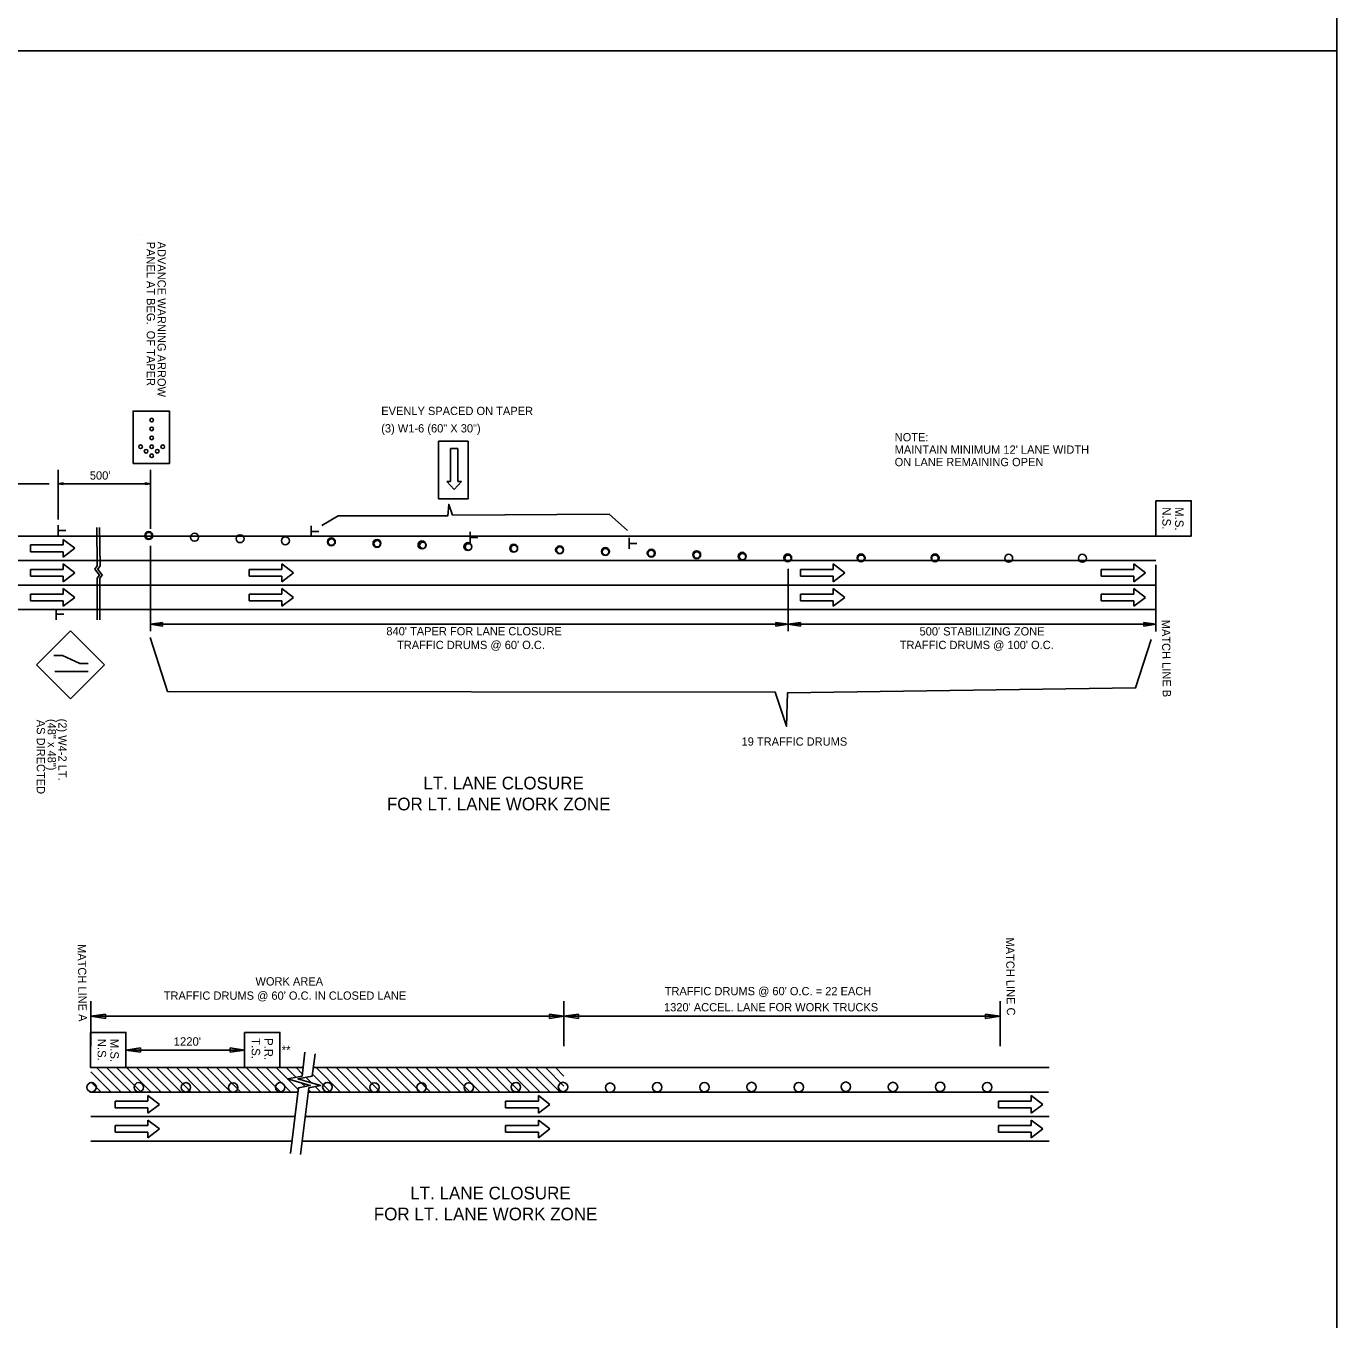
# Model space of a CAD drawing. Extents: x -100 to 745, y -1581 to -107.
# Drawn here: x 252.5 to 345.4, y -460.6 to -368.8 of the extents above; entities that cross this region are included whole.
import ezdxf

# ---------------------------------------------------------------- set-up
doc = ezdxf.new("R2010")
doc.units = 0
for name, color, linetype in [('Default', 7, 'Continuous'), ('R_Contour Annot', 7, 'Continuous'), ('R_Draft', 7, 'Continuous'), ('R_ROW', 7, 'Continuous'), ('R_ROW Annot', 7, 'Continuous')]:
    doc.layers.add(name, color=color, linetype=linetype)

msp = doc.modelspace()

# ---------------------------------------------------------------- linework, layer by layer
at = {"layer": 'Default'}
for p, q in [((282.592, -398.789), (282.592, -401.12)), ((282.592, -398.789), (283.111, -398.789)), ((283.111, -398.789), (283.111, -401.12)), ((254.765, -400.299), (254.765, -403.82)), ((261.312, -400.299), (261.312, -404.481)), ((248.914, -401.278), (254.133, -401.278)), ((255.14, -401.222), (254.765, -401.278)), ((254.765, -401.278), (261.312, -401.278)), ((255.14, -401.335), (254.765, -401.278)), ((255.14, -401.232), (254.828, -401.278)), ((255.14, -401.325), (254.828, -401.278)), ((255.14, -401.241), (254.892, -401.278)), ((255.14, -401.316), (254.892, -401.278)), ((255.14, -401.25), (254.955, -401.278)), ((255.14, -401.306), (254.955, -401.278)), ((255.14, -401.26), (255.018, -401.278)), ((255.14, -401.297), (255.018, -401.278)), ((255.14, -401.27), (255.081, -401.278)), ((255.14, -401.287), (255.081, -401.278)), ((255.14, -401.335), (255.14, -401.222)), ((260.937, -401.222), (261.312, -401.278)), ((260.937, -401.222), (260.937, -401.335)), ((260.937, -401.232), (261.25, -401.278)), ((260.937, -401.241), (261.185, -401.278)), ((260.937, -401.25), (261.123, -401.278)), ((260.937, -401.26), (261.059, -401.278)), ((260.937, -401.27), (260.997, -401.278)), ((260.937, -401.335), (261.312, -401.278)), ((260.937, -401.297), (261.059, -401.278)), ((260.937, -401.316), (261.185, -401.278)), ((260.937, -401.325), (261.25, -401.278)), ((260.937, -401.306), (261.123, -401.278)), ((260.937, -401.287), (260.997, -401.278)), ((282.592, -401.12), (282.333, -401.12)), ((282.333, -401.12), (282.851, -401.689)), ((282.851, -401.689), (283.371, -401.12)), ((283.111, -401.12), (283.371, -401.12)), ((245.32, -404.99), (261.312, -404.99)), ((254.765, -404.994), (254.765, -404.212)), ((254.777, -404.605), (255.311, -404.605)), ((261.312, -404.99), (332.591, -404.99)), ((272.715, -404.268), (272.715, -405.05)), ((272.727, -404.657), (273.261, -404.657)), ((283.986, -404.694), (283.986, -405.477)), ((255.132, -405.622), (252.807, -405.622)), ((252.807, -405.622), (252.807, -406.097)), ((255.132, -405.227), (255.132, -405.622)), ((255.132, -405.227), (255.953, -405.859)), ((255.953, -405.859), (255.132, -406.492)), ((261.312, -411.735), (261.312, -405.691)), ((283.997, -405.083), (284.532, -405.083)), ((295.257, -405.121), (295.257, -405.903)), ((295.268, -405.51), (295.802, -405.51)), ((245.32, -406.729), (261.312, -406.729)), ((255.132, -406.097), (252.807, -406.097)), ((255.132, -406.097), (255.132, -406.492)), ((261.312, -406.729), (332.591, -406.729)), ((255.132, -407.361), (252.807, -407.361)), ((252.807, -407.361), (252.807, -407.835)), ((255.132, -406.966), (255.132, -407.361)), ((255.132, -406.966), (255.953, -407.598)), ((255.953, -407.598), (255.132, -408.23)), ((270.63, -407.361), (268.304, -407.361)), ((268.304, -407.361), (268.304, -407.835)), ((270.63, -406.966), (270.63, -407.361)), ((270.63, -406.966), (271.451, -407.598)), ((271.451, -407.598), (270.63, -408.23)), ((306.513, -411.735), (306.513, -407.306)), ((309.709, -407.361), (307.384, -407.361)), ((307.384, -407.361), (307.384, -407.835)), ((309.709, -406.966), (309.709, -407.361)), ((309.709, -406.966), (310.53, -407.598)), ((310.53, -407.598), (309.709, -408.23)), ((331.029, -407.361), (328.703, -407.361)), ((328.703, -407.361), (328.703, -407.835)), ((331.029, -406.966), (331.029, -407.361)), ((331.029, -406.966), (331.849, -407.598)), ((331.849, -407.598), (331.029, -408.23)), ((332.591, -407.028), (332.591, -411.745)), ((245.32, -408.467), (261.312, -408.467)), ((255.132, -407.835), (252.807, -407.835)), ((255.132, -407.835), (255.132, -408.23)), ((255.132, -408.704), (255.132, -409.099)), ((255.132, -408.704), (255.953, -409.336)), ((261.312, -408.467), (332.591, -408.467)), ((270.63, -407.835), (268.304, -407.835)), ((270.63, -407.835), (270.63, -408.23)), ((270.63, -408.704), (270.63, -409.099)), ((270.63, -408.704), (271.451, -409.336)), ((309.709, -407.835), (307.384, -407.835)), ((309.709, -407.835), (309.709, -408.23)), ((309.709, -408.704), (309.709, -409.099)), ((309.709, -408.704), (310.53, -409.336)), ((331.029, -407.835), (328.703, -407.835)), ((331.029, -407.835), (331.029, -408.23)), ((331.029, -408.704), (331.029, -409.099)), ((331.029, -408.704), (331.849, -409.336)), ((255.132, -409.099), (252.807, -409.099)), ((252.807, -409.099), (252.807, -409.574)), ((255.132, -409.574), (252.807, -409.574)), ((255.953, -409.336), (255.132, -409.969)), ((255.132, -409.574), (255.132, -409.969)), ((270.63, -409.099), (268.304, -409.099)), ((268.304, -409.099), (268.304, -409.574)), ((270.63, -409.574), (268.304, -409.574)), ((271.451, -409.336), (270.63, -409.969)), ((270.63, -409.574), (270.63, -409.969)), ((309.709, -409.099), (307.384, -409.099)), ((307.384, -409.099), (307.384, -409.574)), ((309.709, -409.574), (307.384, -409.574)), ((310.53, -409.336), (309.709, -409.969)), ((309.709, -409.574), (309.709, -409.969)), ((331.029, -409.099), (328.703, -409.099)), ((328.703, -409.099), (328.703, -409.574)), ((331.029, -409.574), (328.703, -409.574)), ((331.849, -409.336), (331.029, -409.969)), ((331.029, -409.574), (331.029, -409.969)), ((245.32, -410.206), (261.312, -410.206)), ((254.639, -410.924), (254.639, -410.141)), ((254.65, -410.535), (255.184, -410.535)), ((261.312, -410.206), (332.591, -410.206)), ((262.182, -411.115), (261.312, -411.246)), ((306.513, -411.246), (261.312, -411.246)), ((261.312, -411.246), (262.182, -411.376)), ((262.182, -411.376), (262.182, -411.115)), ((306.513, -411.246), (305.644, -411.115)), ((305.644, -411.115), (305.644, -411.376)), ((305.644, -411.376), (306.513, -411.246)), ((307.383, -411.115), (306.513, -411.246)), ((332.591, -411.246), (306.513, -411.246)), ((306.513, -411.246), (307.383, -411.376)), ((307.383, -411.376), (307.383, -411.115)), ((332.591, -411.246), (331.722, -411.115)), ((331.722, -411.115), (331.722, -411.376)), ((331.722, -411.376), (332.591, -411.246)), ((255.646, -411.709), (253.237, -414.119)), ((255.646, -411.709), (258.056, -414.119)), ((253.237, -414.119), (255.646, -416.528)), ((254.479, -413.458), (255.092, -413.458)), ((255.092, -413.458), (256.317, -414.02)), ((258.056, -414.119), (255.646, -416.528)), ((256.317, -414.02), (256.9, -414.02)), ((254.53, -414.582), (256.9, -414.582)), ((257.095, -437.957), (257.095, -441.149)), ((290.63, -437.957), (290.63, -441.149)), ((321.54, -437.957), (321.54, -441.149)), ((257.095, -439.036), (258.125, -438.881)), ((290.63, -439.036), (257.095, -439.036)), ((258.125, -439.19), (257.095, -439.036)), ((258.125, -438.881), (258.125, -439.19)), ((289.6, -439.19), (289.6, -438.882)), ((289.6, -438.882), (290.63, -439.036)), ((290.63, -439.036), (289.6, -439.19)), ((290.63, -439.036), (291.66, -438.881)), ((321.54, -439.036), (290.63, -439.036)), ((291.66, -439.19), (290.63, -439.036)), ((291.66, -438.881), (291.66, -439.19)), ((320.51, -439.19), (320.51, -438.881)), ((320.51, -438.881), (321.54, -439.036)), ((321.54, -439.036), (320.51, -439.19)), ((257.095, -439.695), (257.095, -441.149)), ((257.095, -440.627), (257.095, -441.149)), ((259.573, -441.424), (260.604, -441.269)), ((267.994, -441.424), (259.573, -441.424)), ((260.604, -441.578), (259.573, -441.424)), ((260.604, -441.269), (260.604, -441.578)), ((266.964, -441.578), (266.964, -441.269)), ((266.964, -441.269), (267.994, -441.424)), ((267.994, -441.424), (266.964, -441.578)), ((257.073, -442.674), (272.134, -442.674)), ((257.096, -442.973), (258.535, -444.412)), ((257.504, -442.674), (259.242, -444.412)), ((258.211, -442.674), (260.004, -444.468)), ((258.918, -442.674), (260.656, -444.412)), ((259.625, -442.674), (261.363, -444.412)), ((260.332, -442.674), (262.07, -444.412)), ((261.039, -442.674), (262.777, -444.412)), ((261.746, -442.674), (263.485, -444.412)), ((262.453, -442.674), (264.192, -444.412)), ((263.16, -442.674), (264.899, -444.412)), ((263.868, -442.674), (265.606, -444.412)), ((264.575, -442.674), (266.313, -444.412)), ((265.282, -442.674), (267.02, -444.412)), ((265.989, -442.674), (267.727, -444.412)), ((266.696, -442.674), (268.434, -444.412)), ((267.403, -442.674), (269.141, -444.412)), ((268.11, -442.674), (269.849, -444.412)), ((268.817, -442.674), (270.556, -444.412)), ((269.524, -442.674), (271.263, -444.412)), ((270.232, -442.674), (271.801, -444.243)), ((270.939, -442.674), (271.62, -443.355)), ((271.646, -442.674), (272.082, -443.11)), ((272.863, -442.673), (290.63, -442.673)), ((273.06, -442.674), (274.798, -444.412)), ((273.767, -442.674), (275.505, -444.412)), ((274.474, -442.674), (276.212, -444.412)), ((275.181, -442.674), (276.92, -444.412)), ((275.888, -442.674), (277.627, -444.412)), ((276.596, -442.674), (278.334, -444.412)), ((277.303, -442.674), (279.041, -444.412)), ((278.01, -442.674), (279.748, -444.412)), ((278.717, -442.674), (280.455, -444.412)), ((279.424, -442.674), (281.162, -444.412)), ((280.131, -442.674), (281.869, -444.412)), ((280.838, -442.674), (282.576, -444.412)), ((281.545, -442.674), (283.284, -444.412)), ((282.252, -442.674), (283.991, -444.412)), ((282.959, -442.674), (284.698, -444.412)), ((283.667, -442.674), (285.405, -444.412)), ((284.374, -442.674), (286.112, -444.412)), ((285.081, -442.674), (286.819, -444.412)), ((285.788, -442.674), (287.526, -444.412)), ((286.495, -442.674), (288.233, -444.412)), ((287.202, -442.674), (288.94, -444.412)), ((287.909, -442.674), (289.647, -444.412)), ((288.616, -442.674), (290.355, -444.412)), ((289.323, -442.674), (290.63, -443.981)), ((290.031, -442.674), (290.63, -443.274)), ((290.63, -442.673), (325.019, -442.673)), ((257.096, -443.68), (257.828, -444.412)), ((272.029, -443.764), (272.28, -444.015)), ((272.33, -443.358), (272.727, -443.755)), ((272.808, -443.129), (274.091, -444.412)), ((272.99, -444.018), (273.384, -444.412)), ((257.025, -444.412), (271.78, -444.412)), ((261.133, -445.044), (261.133, -444.649)), ((261.954, -445.281), (261.133, -444.649)), ((272.508, -444.412), (290.63, -444.412)), ((272.527, -444.262), (272.677, -444.412)), ((288.812, -445.044), (288.812, -444.649)), ((289.632, -445.281), (288.812, -444.649)), ((290.581, -444.411), (324.97, -444.411)), ((323.754, -445.044), (323.754, -444.649)), ((324.575, -445.281), (323.754, -444.649)), ((261.133, -445.044), (258.808, -445.044)), ((258.808, -445.518), (258.808, -445.044)), ((261.133, -445.518), (258.808, -445.518)), ((261.133, -445.913), (261.954, -445.281)), ((261.133, -445.913), (261.133, -445.518)), ((288.812, -445.044), (286.486, -445.044)), ((286.486, -445.518), (286.486, -445.044)), ((288.812, -445.518), (286.486, -445.518)), ((288.812, -445.913), (289.632, -445.281)), ((288.812, -445.913), (288.812, -445.518)), ((323.754, -445.044), (321.429, -445.044)), ((321.429, -445.518), (321.429, -445.044)), ((323.754, -445.518), (321.429, -445.518)), ((323.754, -445.913), (324.575, -445.281)), ((323.754, -445.913), (323.754, -445.518)), ((257.095, -446.15), (271.563, -446.15)), ((261.133, -446.782), (258.808, -446.782)), ((258.808, -447.257), (258.808, -446.782)), ((261.133, -446.782), (261.133, -446.387)), ((261.954, -447.02), (261.133, -446.387)), ((272.34, -446.15), (290.63, -446.15)), ((288.812, -446.782), (286.486, -446.782)), ((286.486, -447.257), (286.486, -446.782)), ((288.812, -446.782), (288.812, -446.387)), ((289.632, -447.02), (288.812, -446.387)), ((290.63, -446.15), (325.019, -446.15)), ((323.754, -446.782), (321.429, -446.782)), ((321.429, -447.257), (321.429, -446.782)), ((323.754, -446.782), (323.754, -446.387)), ((324.575, -447.02), (323.754, -446.387)), ((261.133, -447.257), (258.808, -447.257)), ((261.133, -447.652), (261.954, -447.02)), ((261.133, -447.652), (261.133, -447.257)), ((288.812, -447.257), (286.486, -447.257)), ((288.812, -447.652), (289.632, -447.02)), ((288.812, -447.652), (288.812, -447.257)), ((323.754, -447.257), (321.429, -447.257)), ((323.754, -447.652), (324.575, -447.02)), ((323.754, -447.652), (323.754, -447.257)), ((257.095, -447.888), (271.346, -447.888)), ((272.074, -447.888), (290.63, -447.888)), ((290.63, -447.888), (325.019, -447.888))]:
    msp.add_line(p, q, dxfattribs=at)
for points in [[(260.087, -399.851), (260.087, -396.128), (262.663, -396.128), (262.663, -399.851)], [(281.738, -402.355), (281.738, -398.268), (283.828, -398.268), (283.828, -402.355)], [(332.591, -402.49), (335.091, -402.49), (335.091, -404.99), (332.591, -404.99)], [(257.073, -440.174), (259.573, -440.174), (259.573, -442.674), (257.073, -442.674)], [(267.994, -440.174), (270.494, -440.174), (270.494, -442.674), (267.994, -442.674)]]:
    msp.add_lwpolyline(points, close=True, dxfattribs=at)
for points in [[(273.468, -404.247), (274.626, -403.566), (282.391, -403.566), (282.459, -402.748), (282.731, -403.497), (293.835, -403.429), (295.129, -404.588)], [(257.506, -404.379), (257.548, -407.089), (257.385, -407.331), (257.702, -407.764), (257.535, -407.964), (257.534, -410.917)], [(257.706, -404.379), (257.747, -407.098), (257.585, -407.339), (257.901, -407.772), (257.735, -407.972), (257.734, -410.917)], [(261.302, -412.175), (262.535, -416.009), (305.6, -416.059), (306.406, -418.478), (306.479, -416.093), (331.147, -415.76), (332.256, -412.325)], [(271.238, -448.753), (271.819, -444.097), (272.645, -443.951), (271.042, -443.465), (272.062, -443.271), (272.265, -441.586)], [(271.955, -448.843), (272.548, -444.097), (273.373, -443.951), (271.771, -443.465), (272.791, -443.271), (272.981, -441.69)]]:
    msp.add_lwpolyline(points, dxfattribs=at)
for centre, radius in [((261.404, -396.764), 0.131), ((261.404, -397.396), 0.131), ((261.404, -398.029), 0.131), ((260.615, -398.661), 0.131), ((261.01, -398.977), 0.131), ((261.404, -398.661), 0.131), ((261.404, -399.294), 0.131), ((261.799, -398.977), 0.131), ((262.194, -398.661), 0.131), ((261.193, -404.957), 0.281), ((261.205, -404.958), 0.229), ((264.442, -405.072), 0.281), ((267.674, -405.175), 0.281), ((270.884, -405.32), 0.281), ((274.141, -405.397), 0.281), ((274.152, -405.416), 0.229), ((277.374, -405.508), 0.281), ((277.389, -405.531), 0.229), ((280.563, -405.618), 0.281), ((280.626, -405.646), 0.229), ((283.814, -405.734), 0.281), ((283.863, -405.76), 0.229), ((287.064, -405.851), 0.281), ((287.1, -405.875), 0.229), ((290.314, -405.967), 0.281), ((290.336, -405.99), 0.229), ((293.564, -406.083), 0.281), ((293.573, -406.104), 0.229), ((296.814, -406.2), 0.281), ((296.81, -406.219), 0.229), ((300.035, -406.31), 0.281), ((300.047, -406.334), 0.229), ((303.26, -406.421), 0.281), ((303.284, -406.449), 0.229), ((306.485, -406.531), 0.281), ((306.508, -406.564), 0.229), ((306.52, -406.563), 0.229), ((311.69, -406.531), 0.281), ((311.697, -406.562), 0.229), ((316.932, -406.532), 0.281), ((316.924, -406.562), 0.229), ((322.151, -406.562), 0.281), ((327.378, -406.562), 0.281), ((257.15, -444.07), 0.333), ((260.491, -444.07), 0.333), ((263.832, -444.071), 0.333), ((267.174, -444.091), 0.333), ((270.515, -444.07), 0.333), ((273.856, -444.059), 0.333), ((277.197, -444.075), 0.333), ((280.538, -444.075), 0.333), ((283.879, -444.075), 0.333), ((287.22, -444.059), 0.333), ((290.561, -444.047), 0.333), ((293.902, -444.095), 0.333), ((297.243, -444.063), 0.333), ((300.584, -444.063), 0.333), ((303.925, -444.047), 0.333), ((307.266, -444.06), 0.333), ((310.607, -444.025), 0.333), ((313.948, -444.047), 0.333), ((317.289, -444.044), 0.333), ((320.63, -444.06), 0.333)]:
    msp.add_circle(centre, radius, dxfattribs=at)
at = {"layer": 'R_Contour Annot'}
for points in [[(175.406, -260.582), (345.406, -260.582), (345.406, -370.582), (175.406, -370.582)], [(175.406, -370.582), (345.406, -370.582), (345.406, -480.582), (175.406, -480.582)]]:
    msp.add_lwpolyline(points, close=True, dxfattribs=at)
at = {"layer": 'R_Draft'}
for points in [[(175.406, -260.582), (175.406, -370.582), (345.406, -370.582), (345.406, -260.582)], [(175.406, -370.582), (175.406, -480.582), (345.406, -480.582), (345.406, -370.582)]]:
    msp.add_lwpolyline(points, close=True, dxfattribs=at)
at = {"layer": 'R_ROW Annot'}
msp.add_line((260.692, -383.596), (260.692, -383.596), dxfattribs=at)
msp.add_line((260.692, -383.596), (260.692, -383.596), dxfattribs=at)

# ---------------------------------------------------------------- texts
at = {"layer": 'Default'}
for s, height, rotation, p in [('PANEL AT BEG.  OF TAPER', 0.5862, 270, (261.055, -384.115)), ('ADVANCE WARNING ARROW', 0.5862, 270, (261.819, -384.115)), ('EVENLY SPACED ON TAPER', 0.5862, 359.99246, (277.676, -396.409)), ('(3) W1-6 (60" X 30")', 0.5862, 359.99246, (277.676, -397.644)), ('N.S.', 0.6, 270, (333.044, -402.949)), ('M.S.', 0.6, 270, (333.944, -402.949)), ('MATCH LINE B', 0.5862, 270.80593, (332.997, -410.926)), ('AS DIRECTED', 0.5862, 270, (253.261, -418.013)), ('(48" x 48")', 0.5862, 270, (254.033, -417.956)), ('(2) W4-2 LT.', 0.5862, 270, (254.79, -417.932)), ('MATCH LINE C', 0.5862, 270.80593, (321.947, -433.454)), ('MATCH LINE A', 0.5862, 270.80593, (256.152, -433.917)), ('N.S.', 0.6, 270, (257.573, -440.632)), ('M.S.', 0.6, 270, (258.473, -440.632)), ('T.S.', 0.6, 270, (268.494, -440.585)), ('P.R.', 0.6, 270, (269.394, -440.585))]:
    msp.add_text(s, height=height, rotation=rotation, dxfattribs=at).set_placement(p)
for s, height, p in [('NOTE:', 0.5862, (314.068, -398.275)), ('ON LANE REMAINING OPEN', 0.5862, (314.068, -400.034)), ("MAINTAIN MINIMUM 12' LANE WIDTH", 0.5862, (314.068, -399.154)), ("500'", 0.5862, (257.023, -400.986)), ("840' TAPER FOR LANE CLOSURE", 0.5862, (278.04, -412.028)), ("500' STABILIZING ZONE", 0.5862, (315.832, -412.038)), ("TRAFFIC DRUMS @ 60' O.C.", 0.5862, (278.796, -413.002)), ("TRAFFIC DRUMS @ 100' O.C.", 0.5862, (314.427, -413.002)), ('19 TRAFFIC DRUMS', 0.5862, (303.215, -419.849)), ('WORK AREA', 0.5862, (268.762, -436.853)), ("TRAFFIC DRUMS @ 60' O.C. IN CLOSED LANE", 0.5862, (262.258, -437.861)), ("TRAFFIC DRUMS @ 60' O.C. = 22 EACH", 0.5862, (297.767, -437.542)), ("1320' ACCEL. LANE FOR WORK TRUCKS", 0.5862, (297.719, -438.685)), ("1220'", 0.6, (262.962, -441.12)), ('**', 0.6, (270.617, -441.724))]:
    msp.add_text(s, height=height, dxfattribs=at).set_placement(p)
at = {"layer": 'R_ROW'}
for s, p in [('LT. LANE CLOSURE ', (280.664, -422.949)), ('FOR LT. LANE WORK ZONE', (278.078, -424.434)), ('LT. LANE CLOSURE ', (279.735, -452.016)), ('FOR LT. LANE WORK ZONE', (277.149, -453.501))]:
    msp.add_text(s, height=0.9, dxfattribs=at).set_placement(p)

doc.saveas('drawing.dxf')
